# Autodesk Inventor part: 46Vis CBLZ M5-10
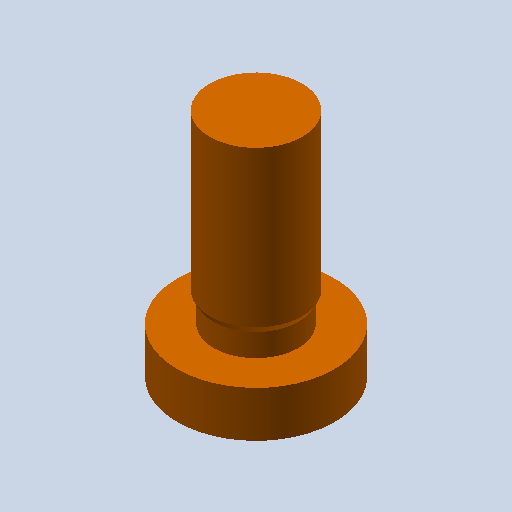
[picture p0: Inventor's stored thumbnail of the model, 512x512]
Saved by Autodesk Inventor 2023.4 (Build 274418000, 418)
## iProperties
Created: 2011-01
Part Number: 46Vis CBLZ M5-10
Document SubType Name: Modeling
Designer: eric
Density: 1 g/cm^3
Mass: 0.349554 g
Surface Area: 3.7092 cm^2
Volume: 0.349554 cm^3
Material: Générique
Appearance: 255,128,0_1
Author: eric
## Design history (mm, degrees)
feature "Base1"
node "Corps solides"
node "Corps surfaciques"
node "Solide1"
